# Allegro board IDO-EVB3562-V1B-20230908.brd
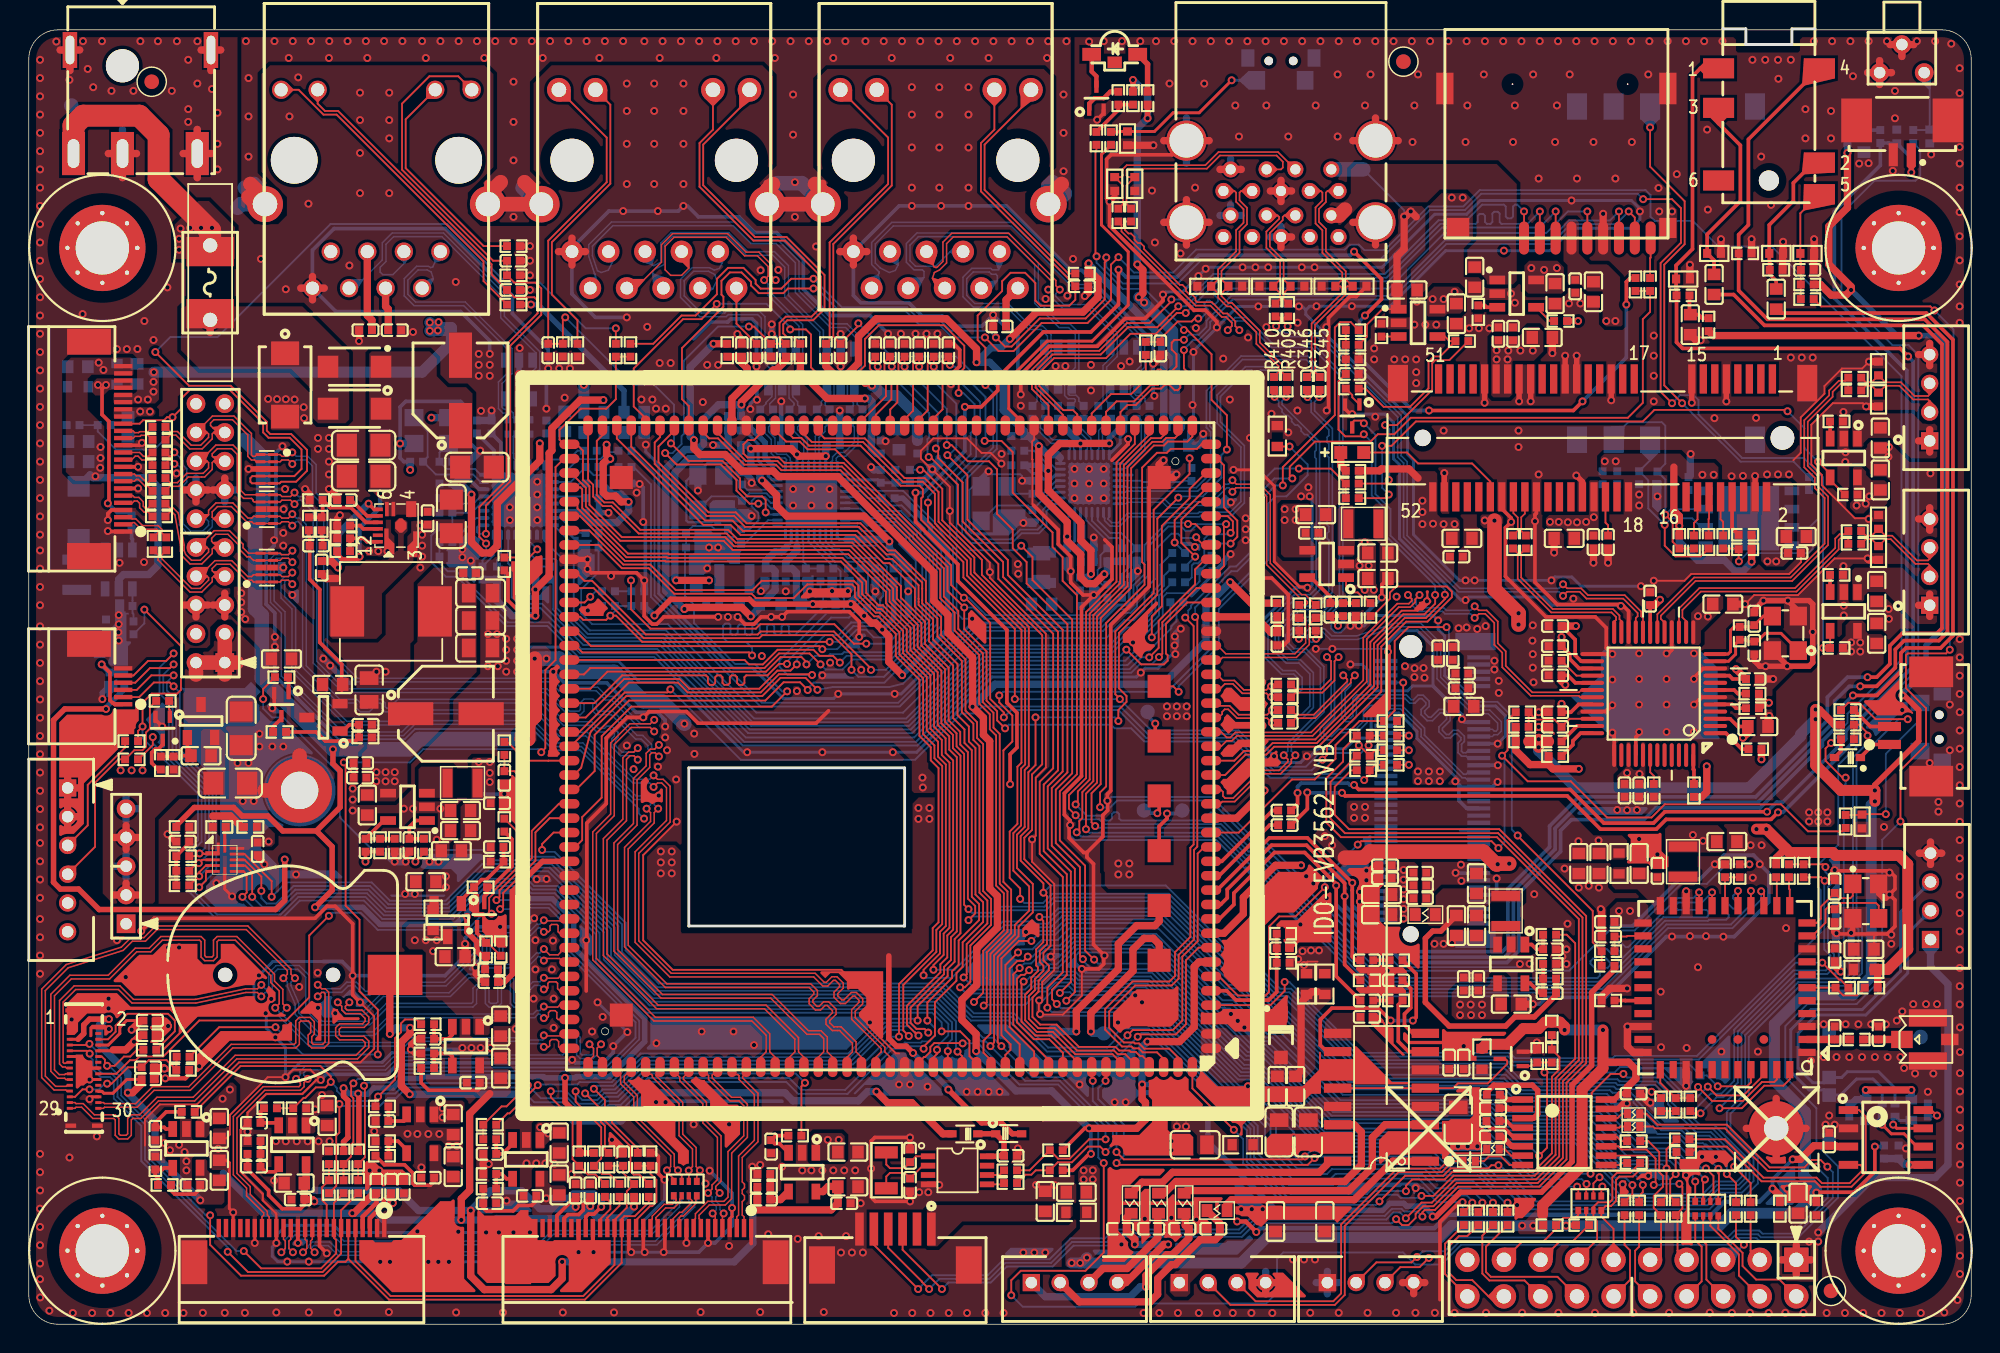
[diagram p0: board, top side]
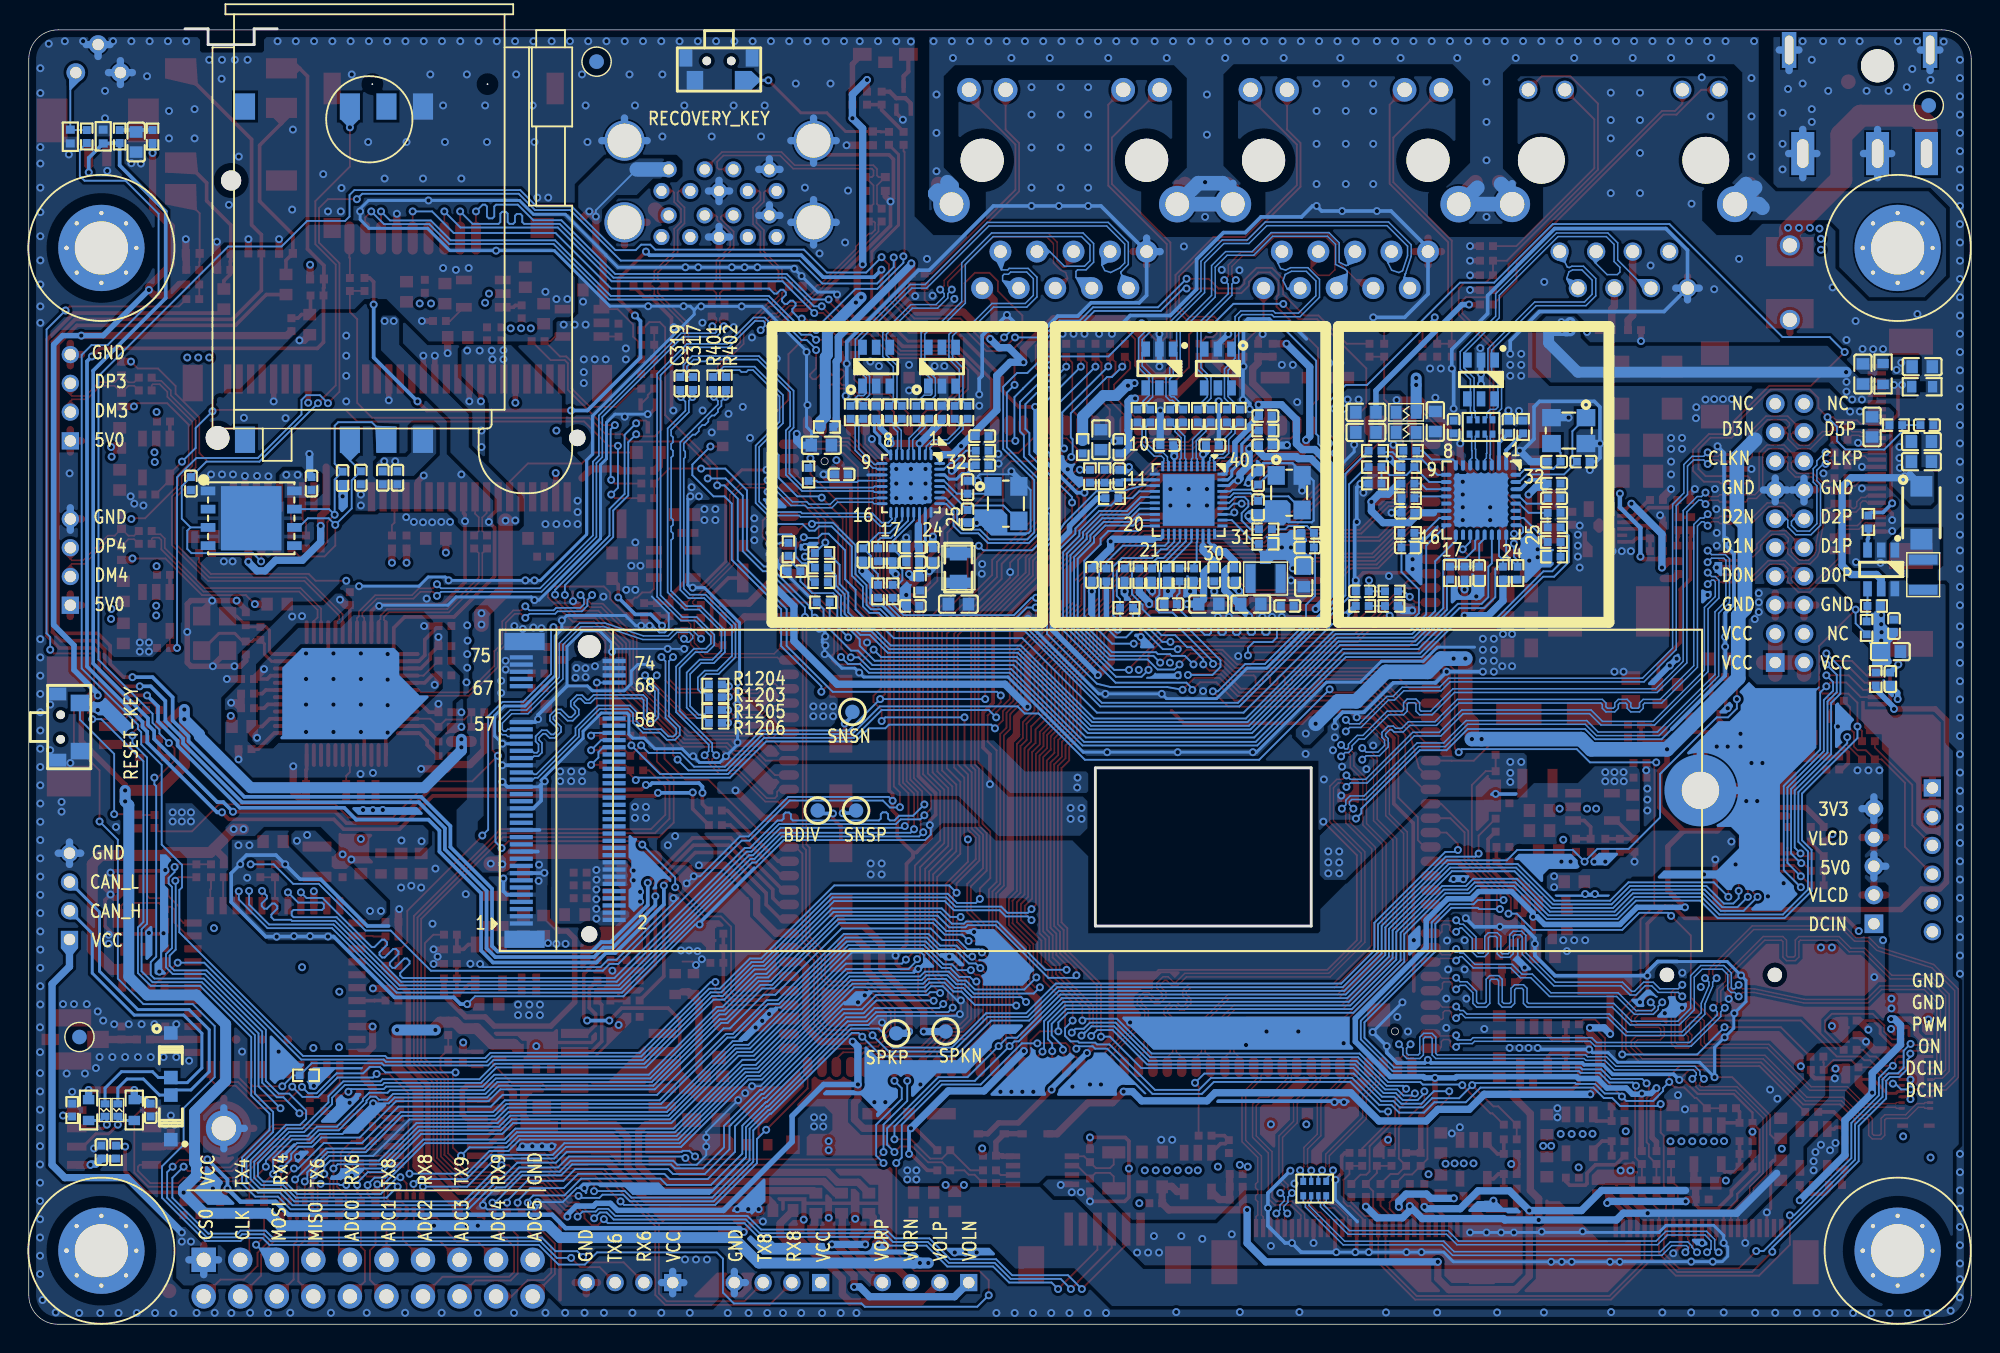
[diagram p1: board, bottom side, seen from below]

Outline 135 x 90.08 mm; copper layers: TOP, L2-VCC, L3-GND, BOTTOM. Coordinates in mm from the lower left corner of the outline.
Outline path: 0,87.97 arc(0.6,89.4) 2.03,90 132.97,90 arc(134.4,89.4) 135,87.97 135,2.03 arc(134.4,0.6) 132.97,0 2.03,0 arc(0.6,0.6) 0,2.03 0,87.97

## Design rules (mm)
net group DIFFPAIR17: nets TXN TXP
net group DIFFPAIR18: nets RXN RXP
net group DIFFPAIR19: nets LAN0_A+ LAN0_A-
net group DIFFPAIR20: nets LAN0_B+ LAN0_B-
net group DIFFPAIR21: nets LAN0_C+ LAN0_C-
net group DIFFPAIR22: nets LAN0_D+ LAN0_D-
net group DIFFPAIR23: nets PHY0_MDI0+ PHY0_MDI0-
net group DIFFPAIR24: nets PHY0_MDI1+ PHY0_MDI1-
net group DIFFPAIR25: nets PHY0_MDI2+ PHY0_MDI2-
net group DIFFPAIR26: nets PHY0_MDI3+ PHY0_MDI3-
net group DIFFPAIR27: nets PHY2_MDI_0+ PHY2_MDI_0-
net group DIFFPAIR28: nets PHY2_MDI_1+ PHY2_MDI_1-
net group DIFFPAIR29: nets PHY2_MDI_2+ PHY2_MDI_2-
net group DIFFPAIR30: nets PHY2_MDI_3+ PHY2_MDI_3-
net group DIFFPAIR31: nets PHY2_MDI3+ PHY2_MDI3-
net group DIFFPAIR32: nets PHY2_MDI2+ PHY2_MDI2-
net group DIFFPAIR33: nets PHY2_MDI1+ PHY2_MDI1-
net group DIFFPAIR34: nets PHY2_MDI0+ PHY2_MDI0-
net group DIFFPAIR35: nets REFCLKN_100M_RJ45 REFCLKP_100M_RJ45
net group DIFFPAIR36: nets PCIE20_REFCLKN PCIE20_REFCLKP
net group DIFFPAIR37: nets PCIE20_REFCLKN_ PCIE20_REFCLKP_
net group DIFFPAIR43: nets MIPI_CSI_RX1_D2N MIPI_CSI_RX1_D2P
net group DIFFPAIR44: nets MIPI_CSI_RX1_D3N MIPI_CSI_RX1_D3P
net group DIFFPAIR45: nets MIPI_CSI_RX1_D1N MIPI_CSI_RX1_D1P
net group DIFFPAIR46: nets MIPI_CSI_RX1_D0N MIPI_CSI_RX1_D0P
net group DIFFPAIR47: nets MIPI_CSI_RX1_CLK0N MIPI_CSI_RX1_CLK0P
net group DIFFPAIR50: nets MIPI_CSI_RX0_CLK1N MIPI_CSI_RX0_CLK1P
net group DIFFPAIR51: nets MIPI_CSI_RX0_D1N MIPI_CSI_RX0_D1P
net group DIFFPAIR52: nets MIPI_CSI_RX0_D0N MIPI_CSI_RX0_D0P
net group DIFFPAIR53: nets MIPI_CSI_RX0_CLK0N MIPI_CSI_RX0_CLK0P
net group USB_PCIE_RX: nets USB_PCIE_RXN USB_PCIE_RXP
net group USB_PCIE_TX: nets USB_PCIE_TXN USB_PCIE_TXP
net group 90OHM: nets 4G_DM 4G_DP HUB_DM1 HUB_DM2 HUB_DM2_2 HUB_DM3 HUB_DM3_2 HUB_DM4 HUB_DM4_2 HUB_DP1 HUB_DP2 HUB_DP2_2 HUB_DP3 HUB_DP3_2 HUB_DP4 HUB_DP4_2 PCIE20_0_TXN PCIE20_0_TXP PCIE20_RXDN PCIE20_RXDP PCIE20_TXDN PCIE20_TXDP PCIE_0_RXN PCIE_0_RXP USB20_HOST1_DM USB20_HOST1_DP USB30_OTG0_DM USB30_OTG0_DP USB30_OTG0_SSRXN/PCIE20_RXDN USB30_OTG0_SSRXP/PCIE20_RXDP USB30_OTG0_SSTXN/PCIE20_TXDN USB30_OTG0_SSTXP/PCIE20_TXDP USB_OTG_DM USB_OTG_DP USB_OTG_SSRXN USB_OTG_SSRXP USB_OTG_SSTXN USB_OTG_SSTXP
net group 100OHM: nets MIPI_CSI1_RX0_D2N MIPI_CSI1_RX0_D2P MIPI_CSI1_RX0_D3N MIPI_CSI1_RX0_D3P MIPI_CSI2_RX0_D2N MIPI_CSI2_RX0_D2P MIPI_CSI2_RX0_D3N MIPI_CSI2_RX0_D3P MIPI_CSI_RX0_D2N MIPI_CSI_RX0_D2P MIPI_CSI_RX0_D3N MIPI_CSI_RX0_D3P MIPI_DSI_TX_CLKN/LVDS_TX_CLKN MIPI_DSI_TX_CLKP/LVDS_TX_CLKP MIPI_DSI_TX_D0N/LVDS_TX_D0N MIPI_DSI_TX_D0P/LVDS_TX_D0P MIPI_DSI_TX_D1N/LVDS_TX_D1N MIPI_DSI_TX_D1P/LVDS_TX_D1P MIPI_DSI_TX_D2N/LVDS_TX_D2N MIPI_DSI_TX_D2P/LVDS_TX_D2P MIPI_DSI_TX_D3N/LVDS_TX_D3N MIPI_DSI_TX_D3P/LVDS_TX_D3P MIPI_TX_CLKN MIPI_TX_CLKP MIPI_TX_D0N MIPI_TX_D0P MIPI_TX_D1N MIPI_TX_D1P MIPI_TX_D2N MIPI_TX_D2P MIPI_TX_D3N MIPI_TX_D3P RN RP TN TP
net group S10: nets CAM_CLK0_OUT_M1 GMAC0_TXCLK_ PMIC_32KOUT_WIFI RGMII_CLK_M0 RGMII_RXCLK_M0 RGMII_TXCLK_M0 RMII_CLK SARADC0_BOOT SARADC0_IN1_KEY/RECOVERY SARADC0_IN3 SARADC0_IN4 SARADC0_IN5 SARADC0_IN6 SARADC0_IN7 SARADC1_IN0 SARADC1_IN1 SARADC1_IN2 SARADC1_IN3 SARADC1_IN4 SARADC1_IN5 SARADC1_IN6 SARADC1_IN7 SD_CLK SDMMC0_CLK SDMMC1_CLK

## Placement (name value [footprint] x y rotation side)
C1  100uF/35V  [CAPAE660X770]  30 64.93 90 top
C2  10uF  [C1206]  29.37 56.17 90 top
C3  10uF  [C1206]  31.15 59.6 180 top
C28  10uF  [C0603]  23.53 36.1 90 top
C29  1uF  [C0402]  23.02 39.02 0 top
C30  100nF  [C0402]  23.02 38.01 0 top
C31  NC/47pF  [C0402]  23.4 33.31 270 top
C32  22uF  [C0603]  30.01 34.32 0 top
C33  22uF  [C0603]  29.37 32.93 0 top
C34  22uF  [C0603]  30 35.72 0 top
C36  100nF  [C0402]  32.54 36.23 180 top
C37  100nF  [C0402]  26.45 33.31 90 top
C39  10uF  [C0603]  128.68 61.63 270 top
C40  10uF  [C0603]  128.68 58.71 90 top
C42  10uF  [C0603]  128.43 50.96 270 top
C43  10uF  [C0603]  128.43 48.04 90 top
C45  10uF  [C0603]  100.49 72.8 270 top
C46  10uF  [C0603]  106.08 71.66 270 top
C53  18pF  [C0402]  119.92 47.02 90 top
C54  18pF  [C0402]  119.92 49.05 90 top
C61  33pF  [C0402]  113.19 58.83 90 bottom
C62  33pF  [C0402]  111.92 58.86 90 bottom
C63  33pF  [C0402]  123.73 58.45 90 bottom
C65  100pF  [C0402]  110.4 58.86 90 bottom
C67  22uF  [C0603]  105.19 68.61 180 top
C68  22uF  [C0603]  99.6 54.64 180 top
C69  22uF  [C0603]  106.71 54.64 0 top
C70  22uF  [C0603]  122.84 54.77 180 top
C74  33pF  [C0402]  99.22 53.37 180 top
C75  33pF  [C0402]  103.16 68.87 270 top
C76  33pF  [C0402]  108.74 54.39 90 top
C77  22uF  [C0603]  89.44 56.29 180 top
C79  47pF  [C0402]  90.46 49.69 270 top
C80  22uF  [C0603]  93.76 51.85 0 top
C81  22uF  [C0603]  93.76 53.63 0 top
C82  1uF  [C0402]  5.62 44.86 90 bottom
C84  1uF  [C0603]  11.97 39.53 0 top
C85  22uF  [C0603]  5.62 46.77 180 bottom
C86  10uF  [C1206]  14 37.62 180 top
C87  100nF  [C0402]  5.37 48.55 90 bottom
C88  10uF  [C1206]  14.76 41.43 90 top
C89  1uF  [C0603]  3.46 59.98 0 bottom
C90  1uF  [C0603]  3.46 61.37 0 bottom
C91  10uF  [C0603]  7.53 66.07 270 bottom
C92  10uF  [C0603]  6.89 62.39 90 bottom
C93  1uF  [C0402]  3.08 62.52 0 bottom
C94  100nF  [C0402]  41.31 11.46 270 top
C95  NC/6.8pF  [C0402]  33.05 38.01 90 top
C96  10uF  [C0603]  13.24 10.7 270 top
C97  10uF  [C0603]  13.24 13.62 90 top
C98  100nF  [C0402]  11.46 9.69 0 top
C99  10uF  [C0603]  32.8 20.73 90 top
C100  10uF  [C0603]  32.8 17.81 270 top
C101  100nF  [C0402]  30.89 16.8 0 top
C102  10uF  [C0603]  56.93 11.97 180 top
C103  10uF  [C0603]  56.93 9.56 180 top
C104  100nF  [C0402]  56.67 8.41 180 top
C105  10uF  [C0603]  20.73 14.51 90 top
C107  10uF  [C0603]  18.45 9.81 0 top
C108  100nF  [C0402]  18.7 8.67 0 top
C112  100pF  [C0402]  56.42 67.72 270 top
C113  100pF  [C0402]  73.19 72.17 0 top
C114  100nF  [C0402]  67.47 69.38 0 top
C115  18pF  [C0402]  69.76 58.2 90 bottom
C116  18pF  [C0402]  69.76 56.17 270 bottom
C126  NC/1uF  [C0402]  73.57 52.99 0 bottom
C128  18pF  [C0402]  49.56 58.83 270 bottom
C129  18pF  [C0402]  49.56 56.8 90 bottom
C130  NC/6.8pF  [C0402]  46.13 54.01 180 bottom
C131  100pF  [C0402]  51.59 67.72 90 top
C132  NC/2.2pF  [C0402]  42.32 50.96 180 bottom
C133  100pF  [C0402]  36.1 67.72 90 top
C143  NC/2.2pF  [C0402]  55.66 50.07 180 bottom
C147  100nF  [C0402]  50.58 67.72 90 top
C150  100pF  [C0402]  33.69 73.95 0 top
C151  NC/6.8pF  [C0402]  81.82 52.36 180 bottom
C152  100pF  [C0402]  33.69 71.91 180 top
C155  NC/6.8pF  [C0402]  39.15 54.01 0 bottom
C156  18pF  [C0402]  28.99 59.98 0 bottom
C158  18pF  [C0402]  26.96 59.98 0 bottom
C159  10uF  [C0603]  42.07 63.41 180 bottom
C160  10uF  [C0603]  37.24 62.77 270 bottom
C163  100nF  [C0402]  25.43 69.12 180 top
C164  10uF  [C0603]  42.07 62.01 180 bottom
C166  100nF  [C0402]  23.4 69.12 0 top
C167  18pF  [C0402]  125.51 28.4 90 top
C168  NC/1pF  [C0402]  125.51 20.25 270 top
C169  NC/1pF  [C0402]  128.56 20.25 270 top
C170  6.8pF  [C0402]  117.89 31.53 270 top
C171  18pF  [C0402]  125.51 30.44 270 top
C176  22uF  [C0603]  127.54 26.07 180 top
C180  NC/6.8pF  [C0402]  109.76 26.96 0 top
C189  11pF  [C0402]  61.25 11.72 270 top
C190  1uF  [C0402]  68.23 11.72 0 top
C191  11pF  [C0402]  61.25 9.68 90 top
C207  1uF  [C0402]  99.73 18.19 270 top
C208  100nF  [C0402]  98.71 18.19 270 top
C209  100nF  [C0402]  93 21.37 180 top
C210  22uF  [C0805]  88.93 13.37 90 top
C211  22uF  [C0805]  86.9 13.37 90 top
C212  22uF  [C0805]  99.35 14.26 90 top
C213  22uF  [C0805]  81.06 12.48 0 top
C214  1uF  [C0402]  95.03 23.91 0 top
C215  100nF  [C0402]  93 22.51 0 top
C216  1nF  [C0402]  80.17 6.64 180 top
C217  1nF  [C0402]  82.33 6.64 180 top
C219  100nF  [C0402]  93 25.31 0 top
C220  1nF  [C0402]  78.01 6.64 180 top
C221  1nF  [C0402]  75.85 6.64 180 top
C222  10uF  [C0603]  121.44 71.28 270 top
C223  NC/100nF  [C0402]  123.6 73.31 180 top
C224  10uF  [C0603]  117.13 72.3 270 top
C226  10uF  [C0603]  72.8 9.18 0 top
C227  10uF  [C0603]  70.64 8.54 270 top
C261  10uF  [C0603]  95.79 71.91 0 top
C262  10uF  [C0603]  99.22 70.26 270 top
C264  10uF  [C0603]  122.97 8.41 270 top
C265  NC/100nF  [C0402]  8.8 13.24 90 top
C266  NC/100nF  [C0402]  27.72 19.84 0 top
C267  NC/100nF  [C0402]  51.59 12.35 90 top
C268  NC/100nF  [C0402]  15.65 14 0 top
C269  1uF  [C0402]  32.16 23.78 0 top
C270  1uF  [C0402]  49.56 67.72 270 top
C271  1uF  [C0402]  86.77 47.66 90 top
C272  1nF  [C0402]  63.91 67.72 270 top
C273  1nF  [C0402]  62.9 67.72 270 top
C274  1nF  [C0402]  61.88 67.72 270 top
C275  1nF  [C0402]  60.87 67.72 270 top
C276  1nF  [C0402]  59.85 67.72 270 top
C277  1nF  [C0402]  58.83 67.72 270 top
C278  10uF  [C0603]  108.74 71.79 90 top
C279  NC/6.8pF  [C0402]  78.65 67.85 90 top
C280  10uF  [C0603]  115.48 69.5 90 top
C281  10uF  [C0603]  127.54 82.2 90 bottom
C282  22uF  [C0603]  88.04 16.54 90 top
C283  22uF  [C0603]  86.77 16.54 90 top
C284  100nF  [C0402]  15.91 33.05 270 top
C285  100nF  [C0402]  10.7 33.56 0 top
C287  100nF  [C0402]  107.47 72.17 90 top
C288  100nF  [C0402]  8.29 17.86 180 top
C289  22uF  [C0603]  94.01 29.88 0 top
C291  33pF  [C0402]  96.68 30.51 180 top
C292  33pF  [C0402]  96.68 31.4 180 top
C293  22uF  [C0603]  99.73 42.96 180 top
C294  33pF  [C0402]  99.6 44.23 180 top
C295  22uF  [C0603]  94.01 28.48 0 top
C301  33pF  [C0402]  99.6 45.24 180 top
C302  100nF  [C0402]  87.18 26.14 180 top
C303  100nF  [C0402]  119.79 44.86 180 top
C304  100nF  [C0402]  111.92 37.12 90 top
C305  100nF  [C0402]  106.08 48.55 0 top
C306  100nF  [C0402]  106.08 42.55 0 top
C307  100nF  [C0402]  110.9 37.12 270 top
C308  100nF  [C0402]  106.08 47.15 180 top
C309  100nF  [C0402]  112.68 50.45 90 top
C310  100nF  [C0402]  106.08 45.12 0 top
C311  NC/100nF  [C0402]  106.08 41.54 0 top
C312  100nF  [C0402]  102.14 68.87 270 top
C313  100nF  [C0402]  122.71 53.63 180 top
C314  100nF  [C0402]  115.35 58.45 270 bottom
C315  100nF  [C0402]  109.38 58.86 90 bottom
C316  100nF  [C0402]  89.19 55.02 180 top
C317  100nF  [C0402]  88.83 65.41 90 bottom
C318  100nF  [C0402]  76.99 53.5 90 bottom
C319  100nF  [C0402]  89.72 65.41 90 bottom
C320  100nF  [C0402]  73.57 49.94 180 bottom
C321  100nF  [C0402]  73.57 54.01 180 bottom
C322  100nF  [C0402]  76.11 63.41 270 bottom
C323  100nF  [C0402]  71.53 63.41 270 bottom
C324  100nF  [C0402]  68.74 59.72 0 bottom
C325  100nF  [C0402]  78.52 59.09 180 bottom
C326  100nF  [C0402]  72.17 53.5 90 bottom
C327  100nF  [C0402]  68.74 61.75 0 bottom
C328  100nF  [C0402]  61.12 52.1 90 bottom
C329  100nF  [C0402]  47.53 49.94 180 bottom
C330  100nF  [C0402]  52.74 61.12 0 bottom
C331  100nF  [C0402]  55.91 61.12 180 bottom
C332  100nF  [C0402]  49.05 61.12 0 bottom
C333  100nF  [C0402]  51.21 52.1 90 bottom
C334  100nF  [C0402]  49.05 63.15 0 bottom
C335  100nF  [C0402]  59.21 60.99 270 bottom
C336  100nF  [C0402]  28.99 58.45 0 bottom
C337  100nF  [C0402]  35.97 62.39 270 bottom
C338  100nF  [C0402]  39.15 56.42 180 bottom
C339  100nF  [C0402]  28.99 57.44 0 bottom
C340  100nF  [C0402]  34.2 52.23 90 bottom
C341  100nF  [C0402]  32.16 62.39 270 bottom
C342  100nF  [C0402]  113.19 31.53 270 top
C343  100nF  [C0402]  109.76 27.97 0 top
C344  100nF  [C0402]  125.51 25.69 90 top
C345  NC/100nF  [C0402]  89.72 65.41 270 top
C346  NC/100nF  [C0402]  88.83 65.41 270 top
C347  100nF  [C0402]  91.98 66.07 180 top
C348  100nF  [C0402]  96.68 29.62 180 top
C349  100nF  [C0402]  94.27 31.91 0 top
C350  100nF  [C0402]  94.27 31.02 0 top
C351  100nF  [C0402]  97.95 46.64 270 top
C352  100nF  [C0402]  98.97 46.64 270 top
C353  NC/100nF  [C0402]  87.28 41.82 180 top
C354  NC/100nF  [C0402]  87.28 42.7 180 top
C355  10uF  [C0603]  120.17 41.56 180 top
C356  10uF  [C0603]  117.74 50.07 180 top
C357  10uF  [C0603]  46.39 51.98 270 bottom
C358  10uF  [C0603]  52.99 50.07 0 bottom
C359  10uF  [C0603]  60.48 61.5 270 bottom
C360  10uF  [C0603]  50.07 50.07 0 bottom
C361  100nF  [C0402]  52.61 52.1 90 bottom
C362  10uF  [C0603]  70.39 50.07 0 bottom
C363  10uF  [C0603]  79.92 61.12 180 bottom
C364  100nF  [C0402]  59.21 58.96 270 bottom
C365  10uF  [C0603]  107.73 32.04 90 top
C366  10uF  [C0603]  111.92 32.04 270 top
C367  10uF  [C0603]  118.02 33.56 180 top
C368  10uF  [C0603]  109.13 32.04 90 top
C369  NC/11pF  [C0402]  15.65 10.95 180 top
C527  100nF  [C0402]  101.76 14.13 180 top
C528  100nF  [C0402]  101.76 13.06 180 top
C529  100nF  [C0402]  101.79 15.96 180 top
C530  100nF  [C0402]  101.76 15.02 180 top
C531  1uF  [C0402]  129.95 11.97 90 bottom
C532  1uF  [C0402]  125.13 12.86 90 top
C533  100nF  [C0402]  126.52 14.89 270 bottom
C806  22uF  [C0805]  31.4 50.83 0 top
C807  10uF  [C1206]  23.27 58.96 0 top
C808  10uF  [C1206]  23.27 61.12 0 top
C809  100nF  [C0402]  27.72 56.04 90 top
C810  100nF  [C0402]  20.35 52.61 270 top
C811  22uF  [C0805]  31.4 48.93 0 top
C812  22uF  [C0805]  31.4 47.02 0 top
C813  22uF  [C0805]  23.65 44.1 90 top
C814  2.2uF  [C0402]  21.88 57.31 180 top
C815  1nF  [C0402]  19.97 54.14 0 top
C870  100uF/35V  [CAPAE660X770]  28.99 42.45 0 top
C871  100nF  [C0402]  30.64 52.23 0 top
C1010  10uF  [C0603]  21.11 44.48 0 top
C1011  10uF  [C0603]  17.56 46.26 0 top
C1012  1uF  [C0402]  23.4 41.69 0 top
C1013  10uF  [C0603]  29.5 13.88 90 top
C1014  NC/100nF  [C0402]  24.54 14.13 0 top
C1015  10uF  [C0603]  29.5 10.95 270 top
C1016  100nF  [C0402]  27.72 10.19 0 top
C1017  10uF  [C0603]  36.86 12.61 90 top
C1018  NC/100nF  [C0402]  32.04 11.84 0 top
C1019  10uF  [C0603]  36.86 9.68 270 top
C1020  100nF  [C0402]  34.83 8.92 0 top
C1022  100nF  [C0402]  26.07 9.56 270 top
C1023  100nF  [C0402]  38.01 9.3 270 top
C1024  100nF  [C0402]  24.16 9.56 270 top
C1025  100nF  [C0402]  32.04 8.41 180 top
C1026  100nF  [C0402]  25.18 9.56 270 top
C1027  100nF  [C0402]  39.02 9.3 270 top
C1028  100nF  [C0402]  8.29 17.03 180 top
C1029  100nF  [C0402]  8.41 21.11 180 top
C1030  100nF  [C0402]  8.41 20.1 180 top
C1031  1uF  [C0603]  3.41 66.58 0 bottom
C1032  10uF  [C0603]  27.59 30.77 0 top
C1033  10uF  [C0603]  29.62 25.56 180 top
C1034  1uF  [C0402]  32.54 33.18 180 top
C1035  100nF  [C0402]  109.76 54.39 90 top
C1036  1uF  [C0402]  111.54 16.03 180 top
C1037  10uF  [C0603]  103.03 22.26 180 top
C1038  1uF  [C0402]  100.74 23.65 270 top
C1039  NC/47pF  [C0402]  105.7 23.02 0 top
C1040  22uF  [C0603]  100.62 30.64 270 top
C1041  22uF  [C0603]  99.22 27.72 90 top
C1042  22uF  [C0603]  100.62 27.72 90 top
C1044  100nF  [C0402]  99.73 23.65 270 top
C1045  100nF  [C0402]  105.7 26.07 180 top
C1046  10uF  [C0603]  86.65 7.14 270 top
C1047  10uF  [C0603]  90.08 7.14 270 top
C1048  11pF  [C0402]  51.09 8.67 180 top
C1049  100nF  [C0402]  87.28 35.72 0 top
C1050  100nF  [C0402]  87.28 34.7 0 top
D1  SM340AF  [SMAF]  22.64 63.66 0 top
D2  SM340AF  [SMAF]  22.64 66.58 0 top
D3  SMBJ30A  [SMB_DO-214AA]  17.81 65.31 270 top
D4  PE0402N12G01B  [V0402]  128.56 64.29 90 top
D5  PE0402N12G01B  [V0402]  128.56 66.45 90 top
D6  PE0402N12G01B  [V0402]  128.56 53.63 90 top
D7  PE0402N12G01B  [V0402]  128.56 55.79 90 top
D8  PE0402N12G01B  [V0402]  88.17 72.17 180 top
D9  PE0402N12G01B  [V0402]  86.01 72.17 180 top
D18  SM340AF  [SMAF]  3.46 56.42 90 bottom
D20  SE05NRC14GA  [DFN2510-10L]  16.54 52.61 90 top
D21  SE05NRC14GA  [DFN2510-10L]  16.54 56.67 90 top
D24  SE05NRC14GA  [DFN2510-10L]  16.54 59.47 270 top
D33  SRV05-4  [SOT23-6]  76.11 66.58 90 bottom
D34  SRV05-4  [SOT23-6]  71.53 66.58 90 bottom
D35  SRV05-4  [SOT23-6]  56.42 66.45 270 bottom
D36  SRV05-4  [SOT23-6]  52.36 66.45 270 bottom
D37  PE0402N12G01B  [V0402]  75.47 79.28 90 top
D38  PE0402N12G01B  [V0402]  76.87 79.28 90 top
D39  PE0402N12G01B  [V0402]  92.49 72.17 180 top
D40  PE0402N12G01B  [V0402]  90.33 72.17 0 top
D41  PE0402N12G01B  [V0402]  83.85 72.17 180 top
D42  PE0402N12G01B  [V0402]  81.69 72.17 0 top
D43  LRB520S-30T1G  [SOD523]  126.4 39.4 180 top
D46  PE0402N12G01B  [V0402]  76.36 82.46 270 top
D48  LRB520S-30T1G  [SOD523]  68.1 13.24 0 top
D49  LRB520S-30T1G  [SOD523]  65.06 13.24 180 top
D50  PE0402N12G01B  [V0402]  127.41 34.96 270 top
D51  PE0402N12G01B  [V0402]  132.11 82.58 270 bottom
D65  PE0402N12G01B  [V0402]  129.83 82.58 90 bottom
D66  PE0402N12G01B  [V0402]  121.44 74.45 0 top
D67  PE0402N12G01B  [V0402]  123.6 74.45 0 top
D68  PE0402N12G01B  [V0402]  117.13 74.45 0 top
D69  PE0402N12G01B  [V0402]  114.97 72.68 0 top
D79  SMF6.0CA  [SOD-123F]  87.03 20.1 90 top
D80  SRV05-4  [SOT23-6]  34.07 65.69 270 bottom
D194  NC/SMF16CA  [SOD-123F]  125.13 18.7 90 bottom
D195  NC/SMF16CA  [SOD-123F]  125.13 14.38 270 bottom
F3  FUSE_30V/2.5A  [SIP2-10D-510]  12.61 72.42 270 top
F4  NC/FUSE_33V/1.1A  [SMD1812]  12.61 72.42 270 top
HOLE5  -  [MTG370_600_VIA]  5.11 5.11 0 top
HOLE9  -  [MTG370_600_VIA]  129.95 74.84 0 top
HOLE10  -  [MTG370_600_VIA]  129.95 5.11 0 top
HOLE11  -  [MTG370_600_VIA]  5.11 74.84 0 top
J1  DC-044A-2_5  [DC-044A-2_0-DIP]  6.51 91.6 270 top
J2  J-H-3P  [PBZ_ICSRC6508SFR]  46.13 14.64 0 top
J3  J-H-3P  [PBZ_ICSRC6508SFR]  34.32 54.13 90 top
J4  J-H-3P  [PBZ_ICSRC6508SFR]  85.38 26.45 90 top
J5  J-H-3P  [PBZ_ICSRC6508SFR]  46.13 65.82 0 top
J6  SD  [TF-01A]  103.92 75.72 180 top
J7  PH2.0-4A  [PH200-4A]  132.11 64.42 270 top
J8  PH2.0-4A  [PH200-4A]  132.11 52.99 270 top
J10  MINI-PCIE-S52-H80  [M_MINIPCIE_SOCKET_CK]  109.38 61.63 0 top
J11  SIM  [SIM-91288-021]  119.92 61.25 270 bottom
J13  FPC05-UD-6P  [FPC05-6P]  4.99 44.36 270 top
J15  -  [HDR200MA-1X5]  6.76 27.85 90 top
J16  -  [HDR200MA-2X10]  13.62 46.01 90 top
J18  FPC05-FDW-30P  [FPC05-30P]  42.96 5.11 0 top
J19  FPC05-PUW-24P  [FPC05-24P]  18.96 5.11 0 top
J20  -  [B2B_30P-40-S]  3.84 17.81 90 top
J21  HY911130A  [RJ45-TH_HY911130A]  63.02 80.93 0 top
J22  HY911130A  [RJ45-TH_HY911130A]  43.47 80.93 0 top
J23  HR911105A  [RJ45-TH_HR911105A]  24.16 80.93 180 top
J24  IPEX_1  [IPEX-001E]  131.99 19.8 180 top
J27  -  [M2_NGFF-M-KEY]  96.04 37.12 180 bottom
J28  MX1.25T-S-3AW  [MX125T-S-3AW]  129.32 41.56 90 top
J35  PH2.0-4A  [PH200-4A]  72.68 2.9 180 top
J36  MX1.25T-S-2A  [MX125T-S-2A]  130.21 80.8 180 top
J37  PJ-316-6A  [PJ-316A-6A]  120.94 90.08 90 top
J42  USB-9AFx2-DIP  [USB-9AF-DIP_2X]  87.03 80.3 180 top
J43  PH2.0-6A  [PH200-6A]  2.7 32.29 90 top
J44  -  [HDR254MA-2X10]  122.84 4.48 180 top
J45  FPC10-FDW-6P  [FPC10-6P]  60.23 6.62 0 top
J46  FPC05-PUW-24P  [FPC05-24P]  4.99 60.87 270 top
J47  -  [CR1220-2P-SMD]  9.56 24.29 0 top
J48  J-H-3P  [PBZ_ICSRC6508SFR]  73.82 65.82 0 top
J49  J-H-3P  [PBZ_ICSRC6508SFR]  73.82 14.64 0 top
J50  J-H-3P  [PBZ_ICSRC6508SFR]  34.32 26.45 90 top
J51  J-H-3P  [PBZ_ICSRC6508SFR]  85.38 54.13 90 top
J54  PH2.0-4A  [PH200-4A]  82.96 2.9 180 top
J55  PH2.0-4A  [PH200-4A]  93.25 2.9 180 top
J56  PH2.0-4A  [PH200-4A]  132.17 29.75 270 top
L3  1uH/3A  [IND_252012]  30.14 37.62 0 top
L7  1uH/3A  [IND_252012]  92.76 55.66 0 top
L8  4.7uH/1.25A  [IND_252012]  3.33 52.12 90 bottom
L11  UPZ1608E101-3R0TF  [L0603]  39.28 62.01 180 bottom
L12  UPZ1608E101-3R0TF  [L0603]  39.28 63.41 0 bottom
L13  4.7uH/1.25A  [IND_252012]  114.97 32.16 90 top
L25  UPZ1608E101-3R0TF  [L0603]  80.3 8.41 270 top
L26  UPZ1608E101-3R0TF  [L0603]  82.58 7.91 180 top
L27  UPZ1608E101-3R0TF  [L0603]  78.52 8.41 270 top
L28  UPZ1608E101-3R0TF  [L0603]  76.61 8.41 270 top
L29  UPZ1608E101-3R0TF  [L0603]  97.06 28.48 180 top
L31  4.7uH/1.25A  [IND_252012]  49.04 51.85 180 bottom
L32  4.7uH/1.25A  [IND_252012]  70.39 52.6 270 bottom
L33  2.2uH/9.5A  [IND_73X66]  25.18 49.56 0 top
L40  GZ1005D121TF  [L0402]  101.76 12.17 180 top
L41  GZ1005D121TF  [L0402]  100.11 11.34 180 top
L42  GZ1005D121TF  [L0402]  111.54 13.75 0 top
L43  GZ1005D121TF  [L0402]  111.54 14.64 0 top
L44  1uH/3A  [IND_252012]  102.65 28.73 90 top
L45  GZ1005D121TF  [L0402]  129.7 14.89 90 bottom
L46  GZ1005D121TF  [L0402]  128.81 14.89 90 bottom
LED1  Yellow LED  [LED-SMD_3_2X1_5X1_0]  75.47 88.3 180 top
LED2  Blue LED0603  [LED0603]  91.98 60.61 0 top
M1  SOM3562  [SOM3562-182P]  37.37 17.69 0 top
M6  SMTSO-M2-2ET  [MTG380_620_SMTSO_M2]  121.44 13.62 0 top
NOREF  -  [unnamed]  125.25 2.32 0 top
NOREF#2  -  [unnamed]  8.54 86.39 0 top
NOREF#3  -  [unnamed]  95.54 87.79 0 top
NOREF#4  -  [unnamed]  2.95 84.74 180 bottom
NOREF#5  -  [unnamed]  131.48 19.97 180 bottom
NOREF#6  -  [unnamed]  95.54 87.79 180 bottom
Q1  MMFTN3019E  [SOT523]  74.2 85.25 90 top
Q3  CJ3401  [SOT23]  11.97 41.94 90 top
Q4  MMFTN3019E  [SOT523]  9.3 41.43 270 top
Q5  MMFTN3019E  [SOT523]  103.03 18.45 180 top
Q6  MMFTN3019E  [SOT523]  91.98 63.15 270 top
Q7  MMFTN3019E  [SOT523]  17.56 43.09 270 top
Q8  CJ3401  [SOT23]  20.48 42.2 180 top
Q9  MMFTN3019E  [SOT523]  31.66 28.48 90 top
Q10  CJ3401  [SOT23]  29.12 28.1 270 top
R4  100K  [R0402]  17.56 44.99 0 top
R8  45.3K  [R0402]  24.42 33.31 270 top
R9  1K  [R0402]  27.46 33.31 90 top
R10  10K  [R0402]  25.43 33.31 90 top
R11  2.2K  [R0402]  71.41 10.7 180 top
R12  2.2K  [R0402]  71.41 12.1 180 top
R13  2.2K  [R0402]  39.28 11.46 270 top
R14  2.2K  [R0402]  38.26 11.46 270 top
R15  2.2K  [R0402]  22.89 11.59 270 top
R16  2.2K  [R0402]  21.88 11.59 270 top
R17  100K  [R0402]  87.18 25.13 0 top
R19  1K  [R0402]  77.76 85.25 90 top
R21  1K  [R0402]  75.72 85.25 90 top
R25  22R  [R0402]  77.63 67.85 90 top
R28  100R  [R0402]  112.68 72.3 90 top
R29  2.2R  [R0402]  126.91 64.93 0 top
R30  2.2R  [R0402]  126.91 65.82 0 top
R31  4.7K  [R0402]  125.64 62.77 0 top
R32  2.2R  [R0402]  126.91 54.26 0 top
R33  2.2R  [R0402]  126.91 55.15 0 top
R34  4.7K  [R0402]  125.64 52.1 0 top
R35  4.7K  [R0402]  100.74 70.39 270 top
R36  0R  [R0402]  103.79 42.55 0 top
R37  2.2R  [R0402]  87.54 70.52 90 top
R38  2.2R  [R0402]  86.65 70.52 90 top
R43  1M  [R0402]  118.9 48.04 90 top
R45  NC/100K  [R0402]  103.79 41.54 180 top
R47  2.7K  [R0402]  106.08 46.13 180 top
R48  0R  [R0402]  103.79 40.52 0 top
R49  0R  [R0402]  104.05 54.39 90 top
R50  0R  [R0402]  103.16 54.39 90 top
R52  0R  [R0402]  119.29 54.9 0 top
R53  15K  [R0402]  119.29 53.88 0 top
R54  22R  [R0402]  117.76 54.39 270 top
R55  22R  [R0402]  116.75 54.39 270 top
R56  22R  [R0402]  115.73 54.39 270 top
R60  53.6K  [R0402]  91.35 49.69 270 top
R62  0R  [R0402]  6.64 44.86 90 bottom
R75  22R  [R0402]  7.27 48.42 90 bottom
R78  1K  [R0402]  40.8 67.72 270 top
R80  100K  [R0402]  10.07 39.02 270 top
R82  100K  [R0402]  6.76 49.94 0 bottom
R84  100K  [R0402]  7.14 55.79 90 bottom
R98  22R  [R0402]  7.14 39.28 180 top
R99  22R  [R0402]  7.14 40.55 180 top
R113  NC/10K  [R0402]  42.07 9.3 270 top
R123  22R  [R0402]  33.05 40.04 270 top
R124  22R  [R0402]  43.09 9.3 270 top
R125  22R  [R0402]  40.29 11.46 270 top
R126  22R  [R0402]  41.05 9.3 270 top
R127  22R  [R0402]  40.04 9.3 270 top
R128  22R  [R0402]  22.89 9.56 270 top
R129  22R  [R0402]  21.88 9.56 270 top
R130  4.7K  [R0402]  11.08 14.76 180 top
R132  49.9K  [R0402]  9.43 9.68 0 top
R133  20K  [R0402]  8.8 11.21 270 top
R134  24.9K  [R0402]  27.72 17.81 180 top
R135  20K  [R0402]  27.72 18.83 0 top
R136  10K  [R0402]  51.09 9.56 180 top
R137  20K  [R0402]  51.09 10.45 0 top
R138  17.4K  [R0402]  15.65 11.84 180 top
R139  20K  [R0402]  15.65 12.73 0 top
R140  2.2R  [R0402]  77.88 63.41 90 bottom
R141  2.2R  [R0402]  75.22 63.41 90 bottom
R142  2.2R  [R0402]  74.33 63.41 90 bottom
R144  2.2R  [R0402]  70.64 63.41 90 bottom
R145  2.2R  [R0402]  69.76 63.41 90 bottom
R147  2.2R  [R0402]  76.99 63.41 90 bottom
R148  2.2R  [R0402]  73.31 63.41 90 bottom
R149  2.2R  [R0402]  72.42 63.41 90 bottom
R150  510R  [R0402]  73.18 73.06 0 top
R153  0R  [R0402]  75.98 50.96 90 bottom
R154  0R  [R0402]  74.96 50.96 90 bottom
R155  0R  [R0402]  80.8 59.09 270 bottom
R156  0R  [R0402]  75.98 53.5 90 bottom
R157  510R  [R0402]  55.4 67.72 270 top
R158  2.49K  [R0402]  68.74 60.74 0 bottom
R159  0R  [R0402]  73.06 51.47 90 bottom
R160  0R  [R0402]  79.53 62.39 180 bottom
R161  NC/1K  [R0402]  74.96 53.5 90 bottom
R162  2.2R  [R0402]  57.94 63.15 90 bottom
R163  2.2R  [R0402]  57.06 63.15 90 bottom
R164  2.2R  [R0402]  55.66 63.15 90 bottom
R165  2.2R  [R0402]  54.77 63.15 90 bottom
R166  2.2R  [R0402]  53.75 63.15 90 bottom
R167  2.2R  [R0402]  52.86 63.15 90 bottom
R168  2.2R  [R0402]  51.72 63.15 90 bottom
R169  2.2R  [R0402]  50.83 63.15 90 bottom
R170  100R  [R0402]  49.05 55.28 0 bottom
R171  120R  [R0402]  46.13 55.02 180 bottom
R172  22R  [R0402]  61.25 58.96 270 bottom
R174  4.7K  [R0402]  49.05 54.26 0 bottom
R175  4.7K  [R0402]  52.61 67.72 270 top
R176  4.7K  [R0402]  37.12 67.72 90 top
R177  22R  [R0402]  40.29 50.96 0 bottom
R178  4.7K  [R0402]  60.1 52.1 270 bottom
R179  4.7K  [R0402]  54.01 52.1 90 bottom
R180  4.7K  [R0402]  55.91 52.1 90 bottom
R181  4.7K  [R0402]  56.93 52.1 90 bottom
R182  NC/4.7K  [R0402]  57.82 52.1 270 bottom
R183  2.49K  [R0402]  49.05 62.14 0 bottom
R184  4.7K  [R0402]  58.83 52.1 90 bottom
R185  NC/4.7K  [R0402]  58.71 49.82 180 bottom
R187  NC/4.7K  [R0402]  40.29 49.94 0 bottom
R188  4.7K  [R0402]  42.32 49.94 0 bottom
R189  510R  [R0402]  53.63 67.72 270 top
R190  100K  [R0402]  60.23 58.96 90 bottom
R191  1.8K  [R0402]  59.72 57.44 0 bottom
R192  22R  [R0402]  55.02 52.1 270 bottom
R193  510R  [R0402]  38.13 67.72 270 top
R194  0R  [R0402]  61.75 60.99 270 bottom
R195  4.7K  [R0402]  39.15 58.45 0 bottom
R196  22R  [R0402]  41.43 59.6 0 bottom
R197  22R  [R0402]  41.43 60.74 0 bottom
R198  22R  [R0402]  79.92 52.61 180 bottom
R199  22R  [R0402]  79.92 53.63 180 bottom
R200  4.7K  [R0402]  33.69 72.93 180 top
R201  22R  [R0402]  79.92 51.59 180 bottom
R202  22R  [R0402]  79.79 50.2 0 bottom
R203  22R  [R0402]  82.2 53.88 270 bottom
R204  NC/4.7K  [R0402]  35.21 52.23 270 bottom
R205  4.7K  [R0402]  31.53 52.23 90 bottom
R206  22R  [RN_0402X4]  34.07 62.39 90 bottom
R207  4.7K  [R0402]  32.54 52.23 90 bottom
R208  22R  [R0402]  36.23 52.23 90 bottom
R209  2.49K  [R0402]  31.15 62.39 90 bottom
R210  22R  [R0402]  28.99 55.4 0 bottom
R211  4.7K  [R0402]  41.43 58.45 0 bottom
R212  NC/4.7K  [R0402]  39.15 59.6 0 bottom
R213  22R  [R0402]  39.15 55.02 180 bottom
R215  22R  [R0402]  28.99 54.39 0 bottom
R216  4.7K  [R0402]  39.15 57.44 0 bottom
R217  4.7K  [R0402]  39.02 60.74 0 bottom
R218  510R  [R0402]  33.69 74.96 180 top
R219  510R  [R0402]  33.69 70.9 180 top
R220  4.7K  [R0402]  28.99 56.42 180 bottom
R225  0R  [R0402]  127.03 19.8 0 top
R227  22R  [R0402]  118.9 31.53 270 top
R229  22R  [R0402]  123.35 31.53 90 top
R235  22R  [R0402]  113.44 15.27 270 top
R237  NC/22R  [R0402]  126.02 23.4 180 top
R238  0R  [R0402]  122.33 31.53 270 top
R239  NC/10K  [R0402]  115.73 17.3 0 bottom
R240  0R  [R0603]  110.52 32.04 270 top
R241  0R  [R0603]  127.54 24.67 180 top
R243  0R  [R0402]  109.76 25.94 0 top
R244  0R  [R0402]  109.76 22.51 0 top
R245  0R  [R0402]  114.46 15.27 90 top
R246  NC/0R  [R0402]  115.48 15.27 90 top
R247  2.2R  [R0402]  75.72 77.12 90 top
R248  2.2R  [R0402]  76.61 77.12 90 top
R253  15K  [R0402]  91.98 67.09 180 top
R258  NC/0R  [R0402]  94.65 39.91 0 top
R259  NC/0R  [R0402]  94.65 40.93 0 top
R260  NC/0R  [R0402]  94.65 38.89 0 top
R261  4.7K  [R0402]  126.4 41.69 180 top
R264  100R  [R0402]  75.22 82.46 90 top
R266  100R  [R0402]  126.27 34.96 90 top
R267  100R  [R0402]  130.97 82.58 90 bottom
R299  0R  [R0603]  101 18.45 270 top
R300  0R  [R0603]  84.36 12.48 180 top
R303  20K  [R0402]  95.03 22.51 0 top
R306  0R  [R0402]  93 23.91 0 top
R308  NC/0R  [R0402]  92.74 39.53 180 top
R309  20K  [R0402]  95.03 25.31 0 top
R310  NC/0R  [R0402]  92.74 40.93 180 top
R311  NC/0R  [R0402]  92.74 38.51 180 top
R314  100K  [R0402]  123.6 72.3 0 top
R316  0R  [R0402]  119.29 74.45 180 top
R318  0R  [R0603]  72.8 7.78 180 top
R341  4.7K  [R0402]  94.01 69.12 90 top
R342  NC/0R  [R0402]  94.65 41.94 0 top
R343  22R  [R0402]  68.23 10.7 180 top
R344  22R  [R0402]  68.23 9.81 180 top
R345  100R  [R0402]  99.73 7.35 270 top
R346  100R  [R0402]  100.74 7.35 270 top
R347  100R  [R0402]  101.76 7.35 270 top
R348  100R  [R0402]  102.78 7.35 270 top
R349  100R  [R0402]  110.9 8.03 270 top
R350  100R  [R0402]  111.92 8.03 270 top
R352  0R  [R0402]  99.6 68.36 180 top
R353  0R  [R0402]  91.98 69.12 180 top
R363  22R  [RN_0402X4]  116.62 8.03 270 top
R365  22R  [RN_0402X4]  108.49 8.41 270 top
R366  0R  [R0402]  121.7 8.03 270 top
R368  22R  [R0402]  119.67 8.03 270 top
R369  22R  [R0402]  118.65 8.03 270 top
R370  22R  [R0402]  114.46 8.03 270 top
R371  22R  [R0402]  113.44 8.03 270 top
R372  22R  [R0402]  10.73 18.6 180 top
R373  4.7K  [R0402]  27.72 20.86 0 top
R374  4.7K  [R0402]  53.25 13.11 180 top
R375  4.7K  [R0402]  16.8 15.02 180 top
R382  0R  [R0402]  32.16 24.67 0 top
R383  0R  [R0402]  48.55 67.72 270 top
R384  0R  [R0402]  86.77 49.69 270 top
R387  2.2K  [R0402]  114.97 71.53 180 top
R388  2.2K  [R0402]  128.68 82.58 270 bottom
R389  47K  [R0402]  87.18 27.16 180 top
R391  10K  [R0402]  109.76 24.92 0 top
R401  0R  [R0402]  87.43 65.41 90 bottom
R402  0R  [R0402]  86.55 65.41 90 bottom
R403  0R  [R0402]  89.44 49.56 90 top
R404  0R  [R0402]  88.3 49.56 90 top
R405  NC/0R  [R0402]  87.28 43.59 0 top
R406  NC/0R  [R0402]  87.28 44.48 0 top
R407  NC/0R  [R0402]  89.44 48.67 270 top
R408  NC/0R  [R0402]  88.3 48.67 270 top
R409  NC/0R  [R0402]  87.43 65.41 90 top
R410  NC/0R  [R0402]  86.55 65.41 90 top
R412  4.99R  [R0603]  3.41 65.18 0 bottom
R413  4.99R  [R0603]  6.13 66.07 270 bottom
R414  0R  [R0402]  112.94 37.12 270 top
R415  10K  [R0402]  76.74 85.25 270 top
R416  0R  [R0402]  8.41 19.08 0 top
R417  NC/10K  [R0402]  10.7 17.69 0 top
R421  2.2K  [R0402]  10.7 32.54 180 top
R422  2.2K  [R0402]  10.7 31.53 180 top
R423  NC/0R  [R0402]  15.4 34.58 180 top
R425  NC/2.2K  [R0402]  107.98 6.89 0 top
R426  NC/2.2K  [R0402]  105.7 6.89 0 top
R429  0R  [R0402]  91.98 58.45 180 top
R430  NC/0R  [R0402]  91.98 57.44 180 top
R431  NC/10K  [R0402]  111.67 72.3 270 top
R434  10K  [R0402]  119.97 39.99 180 top
R435  10K  [R0402]  119.79 42.83 180 top
R436  10K  [R0402]  119.79 43.85 180 top
R437  10K  [R0402]  106.08 40.52 180 top
R438  10K  [R0402]  106.08 39.5 180 top
R439  10K  [R0402]  115.73 37.12 270 top
R440  10K  [R0402]  114.71 54.39 90 top
R441  10K  [R0402]  93.25 49.69 90 top
R442  10K  [R0402]  92.23 49.69 90 top
R443  10K  [R0402]  9.18 39.02 90 top
R444  NC/10K  [R0402]  5.24 62.52 0 bottom
R445  10K  [R0402]  91.98 68.1 0 top
R446  NC/10K  [R0402]  104.83 18.65 90 top
R447  10K  [R0402]  121.44 73.31 180 top
R448  10K  [R0402]  13.24 34.58 180 top
R449  10K  [R0402]  10.7 30.51 180 top
R450  10K  [R0402]  126.65 57.69 0 top
R451  10K  [R0402]  125.64 47.02 0 top
R452  1K  [R0402]  91.98 59.34 0 top
R453  1K  [R0402]  9.3 43.34 0 top
R454  1K  [R0402]  105.85 18.65 270 top
R455  1K  [R0402]  123.6 71.28 180 top
R456  1K  [R0402]  91.98 65.06 180 top
R459  10K  [R0402]  131.99 14.89 90 bottom
R460  0R  [R0402]  128.94 11.97 90 bottom
R461  NC/60.4R  [R0603]  127.67 14.89 90 bottom
R462  NC/60.4R  [R0603]  130.84 14.89 90 bottom
R463  0R  [R0402]  126.4 40.67 180 top
R464  100R  [R0402]  126.4 42.7 0 top
R465  100R  [R0402]  126.4 82.58 90 bottom
R466  100R  [R0402]  116.75 69.5 90 top
R782  47K  [R0402]  21.88 54.64 0 top
R783  100K  [R0402]  21.88 53.75 0 top
R785  10K  [R0402]  21.88 55.53 0 top
R787  73.2K  [R0402]  19.46 55.66 90 top
R1060  10K  [R0402]  19.97 57.31 180 top
R1061  1K  [R0402]  20.35 55.66 90 top
R1062  10K  [R0402]  17.43 41.18 0 top
R1063  100K  [R0402]  23.4 40.8 0 top
R1064  NC/0R  [R0805]  70.39 52.61 270 bottom
R1065  4.7K  [R0402]  24.54 15.15 0 top
R1066  49.9K  [R0402]  24.54 11.72 180 top
R1067  20K  [R0402]  24.54 12.73 0 top
R1068  4.7K  [R0402]  32.04 12.86 0 top
R1069  49.9K  [R0402]  32.04 9.43 180 top
R1070  20K  [R0402]  32.04 10.45 0 top
R1077  NC/0R  [R0402]  124.24 8.03 270 top
R1078  1K  [R0402]  31.78 26.07 90 top
R1079  10K  [R0402]  31.4 30.39 180 top
R1080  100K  [R0402]  32.54 32.16 180 top
R1082  NC/0R  [R0402]  41.82 67.72 270 top
R1083  NC/1K  [R0402]  33.05 34.7 270 top
R1084  NC/0R  [R0603]  28.1 28.1 270 top
R1166  22R  [R0402]  111.54 11.21 180 top
R1167  22R  [R0402]  111.54 12.73 180 top
R1168  10K  [R0402]  106.46 69.76 0 top
R1169  10K  [R0402]  105.7 25.05 180 top
R1170  45.3K  [R0402]  105.7 24.04 0 top
R1171  22R  [R0402]  105.7 27.08 180 top
R1172  NC/0R  [R0402]  32.04 13.88 180 top
R1173  0R  [R0402]  74.2 82.46 270 top
R1174  10K  [R0402]  128.05 23.4 0 top
R1175  NC/22R  [RN_0402X4]  45.63 9.43 270 bottom
R1176  22R  [RN_0402X4]  45.63 9.43 270 top
R1177  120R  [R0402]  20.86 11.59 90 top
R1178  120R  [R0402]  43.21 11.46 90 top
R1179  100R  [R0402]  20.86 9.56 90 top
R1180  100R  [R0402]  42.32 11.46 270 top
R1181  1K  [R0402]  18.83 15.02 0 top
R1182  0R  [R0402]  8.67 54.26 90 top
R1183  0R  [R0402]  9.56 54.26 90 top
R1184  0R  [R0402]  9.05 56.17 180 top
R1185  0R  [R0402]  9.05 57.06 180 top
R1186  0R  [R0402]  9.05 57.94 180 top
R1187  0R  [R0402]  9.05 58.83 180 top
R1188  0R  [R0402]  9.05 59.72 180 top
R1189  0R  [R0402]  9.05 60.61 180 top
R1190  0R  [R0402]  9.05 61.5 180 top
R1191  0R  [R0402]  9.05 62.39 180 top
R1192  10K  [R0402]  32.8 26.07 90 top
R1197  0R  [R0402]  10.7 34.58 180 top
R1198  4.7K  [R0402]  28.99 53.37 180 bottom
R1200  10K  [R0402]  33.05 52.86 270 top
R1201  10K  [R0402]  105.85 20.56 90 top
R1202  NC/0R  [R0603]  86.77 61.75 90 top
R1203  0R  [R0402]  87.28 43.59 0 bottom
R1204  0R  [R0402]  87.28 44.48 0 bottom
R1205  0R  [R0402]  87.28 42.7 0 bottom
R1206  0R  [R0402]  87.28 41.82 0 bottom
R1207  NC/22R  [R0402]  114.97 11.97 0 top
R1208  NC/22R  [R0402]  114.97 12.86 0 top
R1209  0R  [R0603]  88.81 23.65 90 top
R1210  0R  [R0603]  90.08 23.65 90 top
R1211  10K  [R0402]  121.44 31.53 270 top
SW4  T-switch  [PB-SIDE-P-4_5X4_5]  131.73 87.03 270 top
SW5  T-switch  [PB-SIDE-S-3_5X4_5]  87.03 88.04 0 bottom
SW6  T-switch  [PB-SIDE-S-3_5X4_5]  132.99 41.52 270 bottom
TP1  -  [TP100]  77.76 42.58 180 bottom
TP2  -  [TP100]  77.5 35.72 180 bottom
TP3  -  [TP100]  80.17 35.72 180 bottom
TP4  -  [TP100]  74.71 20.23 180 bottom
TP5  -  [TP100]  71.28 20.35 180 bottom
U3  ETA3417S2F  [SOT23-5]  26.32 35.97 180 top
U4  ETA6280S2F  [SOT23-5]  126.14 60.23 270 top
U5  ETA6280S2F  [SOT23-5]  126.14 49.56 270 top
U6  ETA6280S2F  [SOT23-5]  103.41 71.66 0 top
U7  FE1.1  [LQFP-48_7X7X05P]  112.94 43.85 180 top
U8  NC/eSIM  [ESIM]  119.54 56.04 180 bottom
U9  ETA3417S2F  [SOT23-5]  90.2 52.86 180 top
U10  SY7201ABC  [SOT23-6]  6.26 52.48 270 bottom
U11  ETA5050V0S2F  [SOT23-5]  10.95 12.22 270 top
U12  ETA5050V0S2F  [SOT23-5]  30.39 19.34 270 top
U13  ETA5050V0S2F  [SOT23-5]  53.75 10.57 270 top
U14  ETA5050V0S2F  [SOT23-5]  18.32 12.48 270 top
U15  RTL8111HS  [QFN-32_4X4X04P]  73.69 58.45 270 bottom
U16  RTL8211FI-CG  [QFN-40_5X5X04P]  54.39 57.31 270 bottom
U17  RTL8201F-VB-CG  [QFN-32_5X5X05P]  34.07 57.31 270 bottom
U18  AP6256  MODULE  [MD44_AP6XXX]  117.89 23.4 180 top
U20  HYM8563S  [MSOP-8]  64.55 10.7 0 top
U25  NS4205  [SOP16-P127-390X990]  97.06 11.34 180 top
U29  ETA6280S2F  [SOT23-5]  96.55 69.63 0 top
U42  HD3232ECY  [TSSOP-16]  106.73 13.35 0 top
U43  NC/SIT1051T/3  [SOP8-P127-390X490]  129.06 12.99 0 top
U59  ETA4554QHM  [ETA4554-QFN12]  13.62 32.29 0 top
U70  SY8368AQQC  [QFN3X3-12-SY8368AQQC]  25.56 55.53 90 top
U71  ETA5050V0S2F  [SOT23-5]  27.21 13.24 270 top
U72  ETA5050V0S2F  [SOT23-5]  34.58 11.46 270 top
U73  ETA3417S2F  [SOT23-5]  103.03 25.05 270 top
XT1  12MHz  [XTAL_32X25_4P]  122.08 48.04 180 top
XT2  25MHz  [XTAL_32X25_4P]  67.09 57.06 180 bottom
XT3  25MHz  [XTAL_32X25_4P]  47.4 57.82 180 bottom
XT4  25MHz  [XTAL_32X25_4P]  27.97 62.14 270 bottom
XT5  37.4MHz  [XTAL_32X25_4P]  127.67 29.42 0 top
XT6  32.768KHz  [XTAL_32X15_2P]  59.6 10.7 270 top

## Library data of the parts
C1 C870 = C-AL-SMD
C2 C3 C86 C88 C807 C808 = C-1206
C28 C32-C34 C39 C40 C42 C43 C45 C46 C67-C70 C77 C80 C81 C84 C85 C89-C92 C96 C97 C99 C100 C102 C103 C105 C107 C159 C160 C164 C176 C222 C224 C226 C227 C261 C262 C264 C278 C280-C283 C289 C293 C295 C355-C360 C362 C363 C365-C368 C1010 C1011 C1013 C1015 C1017 C1019 C1031-C1033 C1037 C1040-C1042 C1046 C1047 = C-0603
C29-C31 C36 C37 C53 C54 C61-C63 C65 C74-C76 C79 C82 C87 C93-C95 C98 C101 C104 C108 C112-C116 C126 C128-C133 C143 C147 C150-C152 C155 C156 C158 C163 C166-C171 C180 C189-C191 C207-C209 C214-C217 C219-C221 C223 C265-C277 C279 C284 C285 C287 C288 C291 C292 C294 C301-C354 C361 C364 C369 C527-C533 C809 C810 C814 C815 C871 C1012 C1014 C1016 C1018 C1020 C1022-C1030 C1034-C1036 C1038 C1039 C1044 C1045 C1048-C1050 = C-0402
C210-C213 C806 C811-C813 = C-0805
D1-D3 D18 D43 D48 D49 = DI-XI-S
D4-D9 D37-D42 D46 D50 D51 D65-D69 = DI-ESD
D20 D21 D24 = DI-ESD-SE05NRC14GA
D33 D34 D80 = DI-TVS-SRV05-4
D35 D36 = DI-ESD-SRV05-4
D79 D194 D195 = DI-TVS-D
F3 = FUSE-RL30-300-SIP2
F4 = FUSE-SMD1812: User Part Number: HAMP; Tolerance: #TOL
HOLE5 HOLE9-HOLE11 M6 = MH-NOE: User Part Number: pn; Tolerance: RichardLC
J1 = J-DC-044A-2_5
J2-J5 J48-J51 = J-H-3P
J6 = J-TF-01A
J7 J8 J35 J54-J56 = J-H-4P
J10 = J-MINIPCIE-52P_0
J11 = J-SIM-021
J13 J45 = J-FPC-6P
J15 = J-HDR-5: User Part Number: pn; Tolerance: RichardLC
J16 J44 = J-HDR-D-20: User Part Number: pn; Tolerance: RichardLC
J18 = J-FPC-30P
J19 J46 = J-FPC-24P
J20 = J-FPC-30P_1
J21 J22 = J-RJ45-HY911130A: User Part Number: HAMP; Tolerance: #TOL
J23 = J-RJ45-HR911105A_0
J24 = RF-PIEX-1
J27 = J-M2_NGFF-M-KEY_1
J28 = J-A-3P
J36 = J-A-2P
J37 = J-PJ-316A-6A
J42 = J-USB-9AFx2-DIP-W
J43 = J-H-6P
J47 = RTC-VBAT-2P
L3 L7 L8 L13 L31-L33 L44 = L-IND
L11 L12 L25-L29 = FB-0603
L40-L43 L45 L46 = FB-0402
LED1 = D-LED-CT
LED2 = D-LED0603
M1 = SOM3562_3
Q1 Q4-Q7 Q9 = N-MOS-Q
Q3 Q8 Q10 = P-MOS
R4 R8-R17 R19 R21 R25 R28-R38 R43 R45 R47-R50 R52-R56 R60 R62 R75 R78 R80 R82 R84 R98 R99 R113 R123-R130 R132-R142 R144 R145 R147-R150 R153-R172 R174-R185 R187-R205 R207-R213 R215-R220 R225 R227 R229 R235 R237-R239 R243-R248 R253 R258-R261 R264 R266 R267 R303 R306 R308-R311 R314 R316 R341-R350 R352 R353 R366 R368-R375 R382-R384 R387-R389 R391 R401-R410 R414-R417 R421-R423 R425 R426 R429-R431 R434-R456 R459 R460 R463-R466 R782 R783 R785 R787 R1060-R1063 R1065-R1070 R1077-R1080 R1082 R1083 R1166-R1174 R1177-R1192 R1197 R1198 R1200 R1201 R1203-R1208 R1211 = R-0402
R206 R363 R365 R1175 R1176 = RN_0402X4
R240 R241 R299 R300 R318 R412 R413 R461 R462 R1084 R1202 R1209 R1210 = R-0603
R1064 = R-0805
SW4 = SW-3P
SW5 SW6 = SW-TS24CA
TP1-TP5 = TP-TEST: User Part Number: pn; Tolerance: RichardLC
U3 U9 U73 = U-ETA3417S2F
U4-U6 U29 = U-SY6280AAC
U7 = U-FE1_1: User Part Number: HAMP; Tolerance: #TOL
U8 = eSIM: User Part Number: DENG
U10 = U-SY7201ABC
U11-U14 U71 U72 = U-ETA5050
U15 = RL5877_0
U16 = U-RTL8211F-CG
U17 = U-RTL8201F-VB-CG
U18 = MODULE_AP6XXX
U20 = U-HYM8563S
U25 = U-NS4205
U42 = U-SP3232EEN
U43 = U-TJA1057GT-3J
U59 = U-ETA4554QHM
U70 = U-SY8368AQQC_6
XT1 = XTAL-4P_1
XT2-XT5 = XTAL-4P
XT6 = XTAL-2P

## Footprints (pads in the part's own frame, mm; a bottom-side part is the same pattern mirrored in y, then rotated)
B2B_30P-40-S
  rect 0.2x0.42 smd: 1(-2.8,0.99) 2(-2.8,-0.99) 3(-2.4,0.99) 4(-2.4,-0.99) 5(-2,0.99) 6(-2,-0.99) 7(-1.6,0.99) 8(-1.6,-0.99) 9(-1.2,0.99) 10(-1.2,-0.99) 11(-0.8,0.99) 12(-0.8,-0.99) 13(-0.4,0.99) 14(-0.4,-0.99) 15(0,0.99) 16(0,-0.99) 17(0.4,0.99) 18(0.4,-0.99) 19(0.8,0.99) 20(0.8,-0.99) 21(1.2,0.99) 22(1.2,-0.99) 23(1.6,0.99) 24(1.6,-0.99) 25(2,0.99) 26(2,-0.99) 27(2.4,0.99) 28(2.4,-0.99) 29(2.8,0.99) 30(2.8,-0.99)
  rect 0.3x0.75 smd: 31(-4.01,0.925) 32(-4.01,-0.925) 33(4.01,-0.925) 34(4.01,0.925)
C0402
  rect 0.551x0.551 smd: 1(-0.45,0) 2(0.45,0)
C0603
  rect 0.8x0.899 smd: 1(-0.7,0) 2(0.7,0)
C0805
  rect 0.95x1.3 smd: 1(-0.825,0) 2(0.825,0)
C1206
  rect 1.4x1.6 smd: 1(-1.168,0) 2(1.168,0)
CAPAE660X770
  rect 3.15x1.6 smd: 1(-2.45,0) 2(2.45,0)
CR1220-2P-SMD
  round 1.001 hole 1.199 unplated: (4.09,0) (11.59,0)
  rect 3.8x2.799 smd: 1(15.9,0) 2(0,0)
DC-044A-2_0-DIP
  round 2.3 hole 2.3 unplated: (4.1,0)
  rect 3x1.6 hole 2x0.8: 2(10.201,5.199) 3(10.201,0) 4(10.201,-3.401)
  rect 2.5x1 hole 2x0.6: 5(3,6.149) 6(3,-3.65)
DFN2510-10L
  rect 0.2x0.68 smd: 1(-1,-0.437) 2(-0.5,-0.437) 4(0.5,-0.437) 5(1,-0.437) 6(1,0.437) 7(0.5,0.437) 9(-0.5,0.437) 10(-1,0.437)
  rect 0.4x0.75 smd: 3(0,-0.395) 8(0,0.395)
ESIM
  rect 1.016x0.61 smd: 1(-3,1.905) 2(-3,0.635) 3(-3,-0.635) 4(-3,-1.905) 5(3,-1.905) 6(3,-0.635) 7(3,0.635) 8(3,1.905)
  rect 4.216x4.47 smd: 9(0,0)
ETA4554-QFN12
  custom 0.2x0.2 smd: 1(-0.85,0.8)
  rect 1x0.2 smd: 2(-0.85,0.4) 3(-0.85,0) 4(-0.85,-0.4) 5(-0.85,-0.8) 7(0.85,-0.8) 8(0.85,-0.4) 9(0.85,0) 10(0.85,0.4) 11(0.85,0.8)
  rect 0.2x1 smd: 6(0,-1) 12(0,1)
FPC05-6P
  rect 0.305x1.27 smd: 1(1.25,1.575) 2(0.75,1.575) 3(0.25,1.575) 4(-0.25,1.575) 5(-0.75,1.575) 6(-1.25,1.575)
  rect 1.803x3.048 smd: 7(2.95,-0.8) 8(-2.95,-0.8)
FPC05-24P
  rect 0.305x1.27 smd: 1(5.75,1.575) 2(5.25,1.575) 3(4.75,1.575) 4(4.25,1.575) 5(3.75,1.575) 6(3.25,1.575) 7(2.75,1.575) 8(2.25,1.575) 9(1.75,1.575) 10(1.25,1.575) 11(0.75,1.575) 12(0.25,1.575) 13(-0.25,1.575) 14(-0.75,1.575) 15(-1.25,1.575) 16(-1.75,1.575) 17(-2.25,1.575) 18(-2.75,1.575) 19(-3.25,1.575) 20(-3.75,1.575) 21(-4.25,1.575) 22(-4.75,1.575) 23(-5.25,1.575) 24(-5.75,1.575)
  rect 1.803x3.048 smd: 25(7.45,-0.8) 26(-7.45,-0.8)
FPC05-30P
  rect 0.305x1.27 smd: 1(7.25,1.575) 2(6.75,1.575) 3(6.25,1.575) 4(5.75,1.575) 5(5.25,1.575) 6(4.75,1.575) 7(4.25,1.575) 8(3.75,1.575) 9(3.25,1.575) 10(2.75,1.575) 11(2.25,1.575) 12(1.75,1.575) 13(1.25,1.575) 14(0.75,1.575) 15(0.25,1.575) 16(-0.25,1.575) 17(-0.75,1.575) 18(-1.25,1.575) 19(-1.75,1.575) 20(-2.25,1.575) 21(-2.75,1.575) 22(-3.25,1.575) 23(-3.75,1.575) 24(-4.25,1.575) 25(-4.75,1.575) 26(-5.25,1.575) 27(-5.75,1.575) 28(-6.25,1.575) 29(-6.75,1.575) 30(-7.25,1.575)
  rect 1.803x3.048 smd: 31(8.95,-0.8) 32(-8.95,-0.8)
FPC10-6P
  rect 0.6x2.3 smd: 1(2.5,0) 2(1.5,0) 3(0.5,0) 4(-0.5,0) 5(-1.5,0) 6(-2.5,0)
  rect 1.8x2.6 smd: 7(5.1,-2.5) 8(-5.1,-2.5)
HDR200MA-1X5
  rect 1.3x1.3 hole 0.8: 1(0,0)
  round 1.3 hole 0.8: 2(2,0) 3(4,0) 4(6,0) 5(8,0)
HDR200MA-2X10
  rect 1.3x1.3 hole 0.8: 1(0,0)
  round 1.3 hole 0.8: 2(0,2) 3(2,0) 4(2,2) 5(4,0) 6(4,2) 7(6,0) 8(6,2) 9(8,0) 10(8,2) 11(10,0) 12(10,2) 13(12,0) 14(12,2) 15(14,0) 16(14,2) 17(16,0) 18(16,2) 19(18,0) 20(18,2)
HDR254MA-2X10
  rect 1.7x1.7 hole 1: 1(0,0)
  round 1.7 hole 1: 2(0,2.54) 3(2.54,0) 4(2.54,2.54) 5(5.08,0) 6(5.08,2.54) 7(7.62,0) 8(7.62,2.54) 9(10.16,0) 10(10.16,2.54) 11(12.7,0) 12(12.7,2.54) 13(15.24,0) 14(15.24,2.54) 15(17.78,0) 16(17.78,2.54) 17(20.32,0) 18(20.32,2.54) 19(22.86,0) 20(22.86,2.54)
IND_73X66
  rect 2.349x3.5 smd: 1(-3.048,0) 2(3.048,0)
IND_252012
  rect 0.7x2 smd: 1(-1.05,0) 2(1.05,0)
IPEX-001E
  rect 1.2x0.8 smd: 1(-1.525,0)
  rect 1.5x1.2 smd: 2(1.8,0)
  rect 2.65x1.2 smd: 3(0,-1.5) 4(0,1.5)
L0402
  rect 0.49x0.62 smd: 1(-0.43,0) 2(0.43,0)
L0603
  rect 0.75x0.9 smd: 1(-0.7,0) 2(0.7,0)
LED0603
  rect 0.9x0.9 smd: A(-0.8,0) C(0.8,0)
LED-SMD_3_2X1_5X1_0
  rect 1.3x0.9 smd: 1(-1.6,0) 2(1.6,0)
  rect 1x0.8 smd: 3(0,0.55)
LQFP-48_7X7X05P
  oval 1.651x0.279 smd: 1(-4.275,2.751) 2(-4.275,2.25) 3(-4.275,1.75) 4(-4.275,1.25) 5(-4.275,0.749) 6(-4.275,0.249) 7(-4.275,-0.249) 8(-4.275,-0.749) 9(-4.275,-1.25) 10(-4.275,-1.75) 11(-4.275,-2.25) 12(-4.275,-2.751) 25(4.275,-2.751) 26(4.275,-2.25) 27(4.275,-1.75) 28(4.275,-1.25) 29(4.275,-0.749) 30(4.275,-0.249) 31(4.275,0.249) 32(4.275,0.749) 33(4.275,1.25) 34(4.275,1.75) 35(4.275,2.25) 36(4.275,2.751)
  oval 0.279x1.651 smd: 13(-2.751,-4.275) 14(-2.25,-4.275) 15(-1.75,-4.275) 16(-1.25,-4.275) 17(-0.749,-4.275) 18(-0.249,-4.275) 19(0.249,-4.275) 20(0.749,-4.275) 21(1.25,-4.275) 22(1.75,-4.275) 23(2.25,-4.275) 24(2.751,-4.275) 37(2.751,4.275) 38(2.25,4.275) 39(1.75,4.275) 40(1.25,4.275) 41(0.749,4.275) 42(0.249,4.275) 43(-0.249,4.275) 44(-0.749,4.275) 45(-1.25,4.275) 46(-1.75,4.275) 47(-2.25,4.275) 48(-2.751,4.275)
M2_NGFF-M-KEY
  round 1.118 hole 1.118 unplated: (0,-10)
  round 1.6 hole 1.6 unplated: (0,10)
  rect 1.6x0.3 smd: 1(-4.725,-9.25) 2(1.725,-9) 3(-4.725,-8.75) 4(1.725,-8.5) 5(-4.725,-8.25) 6(1.725,-8) 7(-4.725,-7.75) 8(1.725,-7.5) 9(-4.725,-7.25) 10(1.725,-7) 11(-4.725,-6.75) 12(1.725,-6.5) 13(-4.725,-6.25) 14(1.725,-6) 15(-4.725,-5.75) 16(1.725,-5.5) 17(-4.725,-5.25) 18(1.725,-5) 19(-4.725,-4.75) 20(1.725,-4.5) 21(-4.725,-4.25) 22(1.725,-4) 23(-4.725,-3.75) 24(1.725,-3.5) 25(-4.725,-3.25) 26(1.725,-3) 27(-4.725,-2.75) 28(1.725,-2.5) 29(-4.725,-2.25) 30(1.725,-2) 31(-4.725,-1.75) 32(1.725,-1.5) 33(-4.725,-1.25) 34(1.725,-1) 35(-4.725,-0.75) 36(1.725,-0.5) 37(-4.725,-0.25) 38(1.725,0) 39(-4.725,0.25) 40(1.725,0.5) 41(-4.725,0.75) 42(1.725,1) 43(-4.725,1.25) 44(1.725,1.5) 45(-4.725,1.75) 46(1.725,2) 47(-4.725,2.25) 48(1.725,2.5) 49(-4.725,2.75) 50(1.725,3) 51(-4.725,3.25) 52(1.725,3.5) 53(-4.725,3.75) 54(1.725,4) 55(-4.725,4.25) 56(1.725,4.5) 57(-4.725,4.75) 58(1.725,5) 67(-4.725,7.25) 68(1.725,7.5) 69(-4.725,7.75) 70(1.725,8) 71(-4.725,8.25) 72(1.725,8.5) 73(-4.725,8.75) 74(1.725,9) 75(-4.725,9.25)
  rect 2.8x1.2 smd: G1(-4.5,10.35) G2(-4.5,-10.35)
  round 4.5 hole 2.6: G3(77.224,0)
  round 1.27 hole 1.016: G4(77.224,0)
M_MINIPCIE_SOCKET_CK
  round 1.143 hole 1.143 unplated: (-12.499,0)
  round 1.651 hole 1.651 unplated: (12.499,0)
  rect 0.508x2.032 smd: 1(11.801,4.1) 2(11.399,-4.1) 3(11.001,4.1) 4(10.599,-4.1) 5(10.201,4.1) 6(9.799,-4.1) 7(9.4,4.1) 8(8.999,-4.1) 9(8.6,4.1) 10(8.199,-4.1) 11(7.8,4.1) 12(7.399,-4.1) 13(7,4.1) 14(6.599,-4.1) 15(6.2,4.1) 16(5.801,-4.1) 17(2.2,4.1) 18(1.801,-4.1) 19(1.399,4.1) 20(1.001,-4.1) 21(0.599,4.1) 22(0.201,-4.1) 23(-0.201,4.1) 24(-0.599,-4.1) 25(-1.001,4.1) 26(-1.399,-4.1) 27(-1.801,4.1) 28(-2.2,-4.1) 29(-2.601,4.1) 30(-3,-4.1) 31(-3.401,4.1) 32(-3.8,-4.1) 33(-4.201,4.1) 34(-4.6,-4.1) 35(-4.999,4.1) 36(-5.4,-4.1) 37(-5.801,4.1) 38(-6.2,-4.1) 39(-6.599,4.1) 40(-7,-4.1) 41(-7.399,4.1) 42(-7.8,-4.1) 43(-8.199,4.1) 44(-8.6,-4.1) 45(-8.999,4.1) 46(-9.4,-4.1) 47(-9.799,4.1) 48(-10.201,-4.1) 49(-10.599,4.1) 50(-11.001,-4.1) 51(-11.399,4.1) 52(-11.801,-4.1)
  rect 1.397x2.54 smd: 55(-14.224,3.81) 56(14.224,3.81)
MD44_AP6XXX
  rect 1.2x0.5 smd: 1(-5.7,4.5) 2(-5.7,3.6) 3(-5.7,2.7) 4(-5.7,1.8) 5(-5.7,0.9) 6(-5.7,0) 7(-5.7,-0.9) 8(-5.7,-1.8) 9(-5.7,-2.7) 10(-5.7,-3.6) 11(-5.7,-4.5) 23(5.7,-4.5) 24(5.7,-3.6) 25(5.7,-2.7) 26(5.7,-1.8) 27(5.7,-0.9) 28(5.7,0) 29(5.7,0.9) 30(5.7,1.8) 31(5.7,2.7) 32(5.7,3.6) 33(5.7,4.5)
  rect 0.5x1.2 smd: 12(-4.5,-5.7) 13(-3.6,-5.7) 14(-2.7,-5.7) 15(-1.8,-5.7) 16(-0.9,-5.7) 17(0,-5.7) 18(0.9,-5.7) 19(1.8,-5.7) 20(2.7,-5.7) 21(3.6,-5.7) 22(4.5,-5.7) 34(4.5,5.7) 35(3.6,5.7) 36(2.7,5.7) 37(1.8,5.7) 38(0.9,5.7) 39(0,5.7) 40(-0.9,5.7) 41(-1.8,5.7) 42(-2.7,5.7) 43(-3.6,5.7) 44(-4.5,5.7)
  round 0.6 smd: 45(-2.7,3.6) 46(-0.9,3.6) 47(0.9,3.6)
MSOP-8
  rect 1x0.4 smd: 1(-2.05,0.975) 2(-2.05,0.325) 3(-2.05,-0.325) 4(-2.05,-0.975) 5(2.05,-0.975) 6(2.05,-0.325) 7(2.05,0.325) 8(2.05,0.975)
MTG370_600_VIA
  round 0.95 hole 0.3: (-2.425,0) (-1.715,1.715) (-1.715,-1.715) (0,2.425) (0,-2.425) (1.715,1.715) (1.715,-1.715) (2.425,0) (2.425,0)
  round 6 hole 3.7: 1(0,0)
MTG380_620_SMTSO_M2
  round 3.8 hole 1.7: 1(0,0)
MX125T-S-2A
  rect 0.635x1.6 smd: 1(-0.625,-0.508) 2(0.625,-0.508)
  rect 2.134x3.048 smd: 3(-3.175,-2.9) 4(3.175,-2.9)
MX125T-S-3AW
  rect 0.635x1.6 smd: 1(-1.25,0) 2(0,0) 3(1.25,0)
  rect 2.134x3.048 smd: 4(-3.8,-2.9) 5(3.8,-2.9)
PB-SIDE-P-4_5X4_5
  round 1.3 hole 0.8: 1(0,0) 2(0,-3.1) 3(-1.95,-1.55)
PB-SIDE-S-3_5X4_5
  round 0.6 hole 0.6 unplated: (-0.851,0.203) (0.851,0.203)
  rect 0.9x1.2 smd: 1(2.301,0) 2(-2.301,0)
  rect 1.15x1.3 smd: 3(1.675,1.55) 4(-1.675,1.55)
PBZ_ICSRC6508SFR
  rect 0.8x0.8 smd: 1(0,0)
  rect 2x0.8 smd: 2(-2.25,0) 3(2.25,0)
PH200-4A
  rect 1.2x1.2 hole 0.8: 1(3,0)
  round 1.2 hole 0.8: 2(1,0) 3(-1,0) 4(-3,0)
PH200-6A
  rect 1.2x1.2 hole 0.8: 1(5,0)
  round 1.2 hole 0.8: 2(3,0) 3(1,0) 4(-1,0) 5(-3,0) 6(-5,0)
PJ-316A-6A
  round 1.397 hole 1.397 unplated: (-10.55,0)
  rect 1.4x2.159 smd: 1(-2.75,3.496) 2(-9.3,-3.515) 3(-5.5,3.496) 4(-2.75,-3.515) 5(-11.5,-3.515) 6(-10.55,3.496)
QFN3X3-12-SY8368AQQC
  custom 0.175x0.175 smd: 1(-1.1,0.5) 3(-1.3,-1.1)
  custom 0.2x0.2 smd: 2(0,-0.3)
  rect 1.1x0.7 smd: 4(1.15,-1.02)
  rect 1x0.254 smd: 5(1.15,0.225) 6(1.15,0.675)
  rect 0.25x0.7 smd: 7(1.125,1.3) 8(0.675,1.3) 9(0.225,1.3) 10(-0.225,1.3) 11(-0.675,1.3) 12(-1.125,1.3)
QFN-32_4X4X04P
  oval 0.762x0.203 smd: 1(-2,1.4) 2(-2,1) 3(-2,0.6) 4(-2,0.2) 5(-2,-0.2) 6(-2,-0.6) 7(-2,-1) 8(-2,-1.4) 17(2,-1.4) 18(2,-1) 19(2,-0.6) 20(2,-0.2) 21(2,0.2) 22(2,0.6) 23(2,1) 24(2,1.4)
  oval 0.203x0.762 smd: 9(-1.4,-2) 10(-1,-2) 11(-0.6,-2) 12(-0.2,-2) 13(0.2,-2) 14(0.6,-2) 15(1,-2) 16(1.4,-2) 25(1.4,2) 26(1,2) 27(0.6,2) 28(0.2,2) 29(-0.2,2) 30(-0.6,2) 31(-1,2) 32(-1.4,2)
  rect 2.718x2.718 smd: 33(0,0)
QFN-32_5X5X05P
  custom 0.07x0.07 smd: 1(-2.4,1.751) 2(-2.4,1.251) 3(-2.4,0.751) 4(-2.4,0.25) 5(-2.4,-0.25) 6(-2.4,-0.751) 7(-2.4,-1.251) 8(-2.4,-1.751) 9(-1.751,-2.4) 10(-1.251,-2.4) 11(-0.751,-2.4) 12(-0.25,-2.4) 13(0.25,-2.4) 14(0.751,-2.4) 15(1.251,-2.4) 16(1.751,-2.4) 17(2.4,-1.751) 18(2.4,-1.251) 19(2.4,-0.751) 20(2.4,-0.25) 21(2.4,0.25) 22(2.4,0.751) 23(2.4,1.251) 24(2.4,1.751) 25(1.751,2.4) 26(1.251,2.4) 27(0.751,2.4) 28(0.25,2.4) 29(-0.25,2.4) 30(-0.751,2.4) 31(-1.251,2.4) 32(-1.751,2.4)
  rect 3.607x3.607 smd: 33(0,0)
QFN-40_5X5X04P
  rect 0.7x0.2 smd: 1(-2.35,1.8) 2(-2.35,1.4) 3(-2.35,1) 4(-2.35,0.6) 5(-2.35,0.2) 6(-2.35,-0.2) 7(-2.35,-0.6) 8(-2.35,-1) 9(-2.35,-1.4) 10(-2.35,-1.8) 21(2.35,-1.8) 22(2.35,-1.4) 23(2.35,-1) 24(2.35,-0.6) 25(2.35,-0.2) 26(2.35,0.2) 27(2.35,0.6) 28(2.35,1) 29(2.35,1.4) 30(2.35,1.8)
  rect 0.2x0.7 smd: 11(-1.8,-2.35) 12(-1.4,-2.35) 13(-1,-2.35) 14(-0.6,-2.35) 15(-0.2,-2.35) 16(0.2,-2.35) 17(0.6,-2.35) 18(1,-2.35) 19(1.4,-2.35) 20(1.8,-2.35) 31(1.8,2.35) 32(1.4,2.35) 33(1,2.35) 34(0.6,2.35) 35(0.2,2.35) 36(-0.2,2.35) 37(-0.6,2.35) 38(-1,2.35) 39(-1.4,2.35) 40(-1.8,2.35)
  rect 3.2x3.2 smd: 41(0,0)
R0402
  rect 0.551x0.551 smd: 1(-0.45,0) 2(0.45,0)
R0603
  rect 0.65x0.8 smd: 1(-0.725,0) 2(0.725,0)
R0805
  rect 1x1.2 smd: 1(-1,0) 2(1,0)
